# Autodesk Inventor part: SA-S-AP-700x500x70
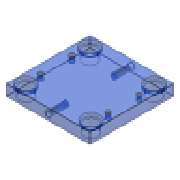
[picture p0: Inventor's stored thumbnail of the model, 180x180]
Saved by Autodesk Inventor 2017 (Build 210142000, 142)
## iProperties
Created: 2016-02
Part Number: SA-S-AP-700x500x70
Material: S 55 C
Description: Cavity Plate
Document SubType Name: Modeling
Designer: Sandeep
Standard Revision: 1
Manufacturer: FUTABA
Language: en-US
Size Designation: 700x500x70
Categories: <MemberInstance><Categories><Category DisplayName="Mold" InternalName="349578f2-f4d4-4954-8c09-8e99297a61c0" Mnemonic="MOLD"><Category DisplayName="Mold Plates"
Density: 7.85 g/cm^3
Appearance: Clear - Blue
IsCustomPart: 1
Author: Sandeep
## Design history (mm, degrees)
sketch "Sketch1"
  geometry: L1 (-250, 350)-(250, 350); L2 (250, 350)-(250, -350); L3 (250, -350)-(-250, -350); L4 (-250, -350)-(-250, 350); 3 further points
  constraints: 8 end point, 2 midpoint, 2 parallel, 1 horizontal, 1 horizontal alignment, 1 perpendicular, 1 vertical alignment
  dimensions: "d123" = 500 distance between parallel lines of L2 L4 (= W_); "d124" = 700 distance between parallel lines of L3 L1 (= L)
extrude "Extrusion1" new body sketch "Sketch1" distance "d20" = 70 (= H_); taper "d30" = 0 deg
sketch "Sketch2"
  geometry: 4 further points
  constraints: 1 horizontal alignment
  dimensions: "d125" = 205 horizontal distance of point (0, 0) point (-205, 243) (= 0.5 x S1_W); "d126" = 243 vertical distance of point (0, 0) point (-205, 243) (= 0.5 x S1_L); "d127" = 207 horizontal distance of point (0, 0) point (-207, 307) (= 0.5 x GB_W); "d128" = 307 vertical distance of point (0, 0) point (-207, 307) (= 0.5 x GB_L); "d129" = 207 horizontal distance of point (0, 0) point (207, 307) (= 0.5 x GB_W)
feature "Sculpt1"
feature "Sculpt2"
thread "Thread1" dims "d191" = 0, "d192" = 0
feature "Sculpt5"
body "Solid1"
sketch "Sketch3"
  geometry: L1 (500, 0)-(0, 0) reference; 3 further points
  constraints: 1 midpoint, 1 vertical alignment
  dimensions: "d169" = 35 distance from line of L1 point (250, 35) (= 0.5 x H_)
hole "Hole1" sketch "Sketch3" diameter "d170" = 31.67; stored, may be unused: countersink angle "d174" = 90 deg, drill point angle "d176" = 118 deg; dims "d171" = 59 (= le), "d172" = 4, "d173" = 2, "d175" = 82 (= ke)
sketch "Sketch4"
  geometry: L1 (0, 0)-(500, 0) reference; 4 further points
  constraints: 2 midpoint, 2 vertical alignment
  dimensions: "d177" = 35 distance from line of L1 point (250, -35) (= 0.5 x H_)
hole "Hole2" sketch "Sketch4" diameter "d178" = 31.67; stored, may be unused: countersink angle "d182" = 90 deg, drill point angle "d184" = 118 deg; dims "d179" = 59 (= le), "d180" = 4, "d181" = 2, "d183" = 82 (= ke)
hole "Hole3" sketch "Sketch2" diameter "d130" = 55 (= GB_d1); stored, may be unused: countersink angle "d134" = 90 deg, drill point angle "d136" = 0 deg; dims "d131" = 6, "d132" = 62 (= GB_d2), "d133" = 10 (= GB_k), "d135" = 70 (= H_)
pattern_linear "Rectangular Pattern1" dims "d159" = 614 (computed from GB_L, Nl)
hole "Hole4" sketch "Sketch2" diameter "d137" = 55 (= GB_d1); stored, may be unused: countersink angle "d141" = 90 deg, drill point angle "d143" = 0 deg; dims "d138" = 6, "d139" = 62 (= GB_d2), "d140" = 10 (= GB_k), "d142" = 70 (= H_)
pattern_linear "Rectangular Pattern2" dims "d162" = 612 (computed from GB_L2, GB_L1, Nl)
hole "Hole5" sketch "Sketch2" diameter "d144" = 13.835; stored, may be unused: countersink angle "d148" = 90 deg, drill point angle "d150" = 118 deg; dims "d145" = 20 (= H_l), "d146" = 62 (= GB_d2), "d147" = 10 (= GB_k), "d149" = 30 (= H_u)
pattern_linear "Rectangular Pattern3" dims "d153" = 243 (computed from S1_L, Ns), "d156" = 410 (computed from S1_W, Nw)
chamfer "Chamfer1" distance "d185" = 0.5; stored, may be unused: second distance "d186" = 2, angle "d187" = 45 deg
feature "Surface1"
body "Srf1"
feature "Surface2"
body "Srf2"
feature "Surface5"
body "Srf5"
other parameters: "L" = 700 [user parameter; used in 1 equation term], "W_" = 500 [user parameter; used in 1 equation term], "H_" = 70 [user parameter; used in 5 equation terms], "GB_W" = 414 [user parameter; used in 2 equation terms], "GB_d1" = 55 [user parameter; used in 2 equation terms], "GB_d2" = 62 [user parameter; used in 3 equation terms], "GB_k" = 10 [user parameter; used in 3 equation terms], "S1_L" = 486 [user parameter; used in 2 equation terms], "GB_L1" = 307 [user parameter; used in 1 equation term], "GB_L2" = 305 [user parameter; used in 1 equation term], "GB_L" = 614 [user parameter; used in 2 equation terms], "le" = 59 [user parameter; used in 2 equation terms], "ke" = 82 [user parameter; used in 2 equation terms], "H_l" = 20 [user parameter; used in 1 equation term], "H_u" = 30 [user parameter; used in 1 equation term]
